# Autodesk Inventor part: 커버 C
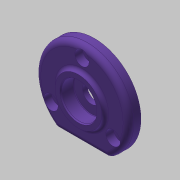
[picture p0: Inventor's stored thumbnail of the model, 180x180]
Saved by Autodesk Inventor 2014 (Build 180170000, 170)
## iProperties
Created: 2020-04
Part Number: 커버 C
Material: 알루미늄 6061
Document SubType Name: Modeling
Designer: mduedu
Density: 2.71 g/cm^3
Appearance: Violet
Mass: 35.2365 g
Surface Area: 62.3737 cm^2
Volume: 13.0024 cm^3
Author: mduedu
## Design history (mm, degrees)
sketch "스케치1"
  geometry: C1 r 26 at (0, 0); 1 further point
  constraints: 1 centre point, 1 coincident
  dimensions: "d0" = 52 diameter of C1
extrude "돌출1" new body sketch "스케치1" distance "d1" = 7; taper "d2" = 0 deg
sketch "스케치2"
  geometry: L1 (-14.62, -21.5)-(14.62, -21.5); A1 r 26 centre (0, 0) between (-14.62, -21.5) and (14.62, -21.5) reference; 1 further point
  constraints: 2 end point, 2 point on circle, 1 horizontal
  dimensions: "d3" = 21.5 distance from line of L1 point (0, 0)
extrude "돌출2" cut sketch "스케치2" stored distance "d4" = 7; taper "d5" = 0 deg
sketch "스케치6"
  geometry: C1 r 13 at (0, 0); 1 further point
  constraints: 1 centre point, 1 coincident
  dimensions: "d29" = 26 diameter of C1
extrude "돌출5" join sketch "스케치6" distance "d30" = 2; taper "d31" = 0 deg
fillet "모깎기1" dims "d6" = 3
fillet "모깎기2" dims "d7" = 3
fillet "모깎기4" dims "d33" = 2
sketch "스케치3" dims "d8" = 40
  geometry: 3 further points
  constraints: 2 vertical alignment, 1 coincident, 2 other
hole "구멍1" sketch "스케치3" at (0, 20) diameter "d9" = 4.5; stored, may be unused: countersink angle "d13" = 90 deg, drill point angle "d15" = 118 deg; dims "d10" = 6, "d11" = 8, "d12" = 4.4, "d14" = 8
sketch "스케치4"
  geometry: C1 r 14 at (0, 0); 1 further point
  constraints: 1 centre point, 1 coincident
  dimensions: "d19" = 28 diameter of C1
extrude "돌출3" join sketch "스케치4" distance "d20" = 4; taper "d21" = 0 deg
sketch "스케치5"
  geometry: C1 r 12 at (0, 0); 1 further point
  constraints: 1 centre point, 1 coincident
  dimensions: "d22" = 24 diameter of C1
extrude "돌출4" cut sketch "스케치5" distance "d23" = 3; taper "d24" = 0 deg
fillet "모깎기3" dims "d25" = 3
chamfer "모따기1" distance "d26" = 0.5; stored, may be unused: second distance "d27" = 2, angle "d28" = 45 deg
sketch "스케치7"
  geometry: 2 further points
  constraints: 1 coincident
hole "구멍2" sketch "스케치7" at (0, 0) diameter "d34" = 10; stored, may be unused: countersink angle "d38" = 90 deg, drill point angle "d40" = 118 deg; dims "d35" = 6, "d36" = 20, "d37" = 7.3, "d39" = 8
fillet "모깎기5" dims "d41" = 0.3
chamfer "모따기2" distance "d42" = 0.7; stored, may be unused: second distance "d43" = 2, angle "d44" = 30 deg
node "솔리드1"
pattern_circular "원형 패턴1" dims angle "d17" = 360 deg
node "투영된 루프1"
